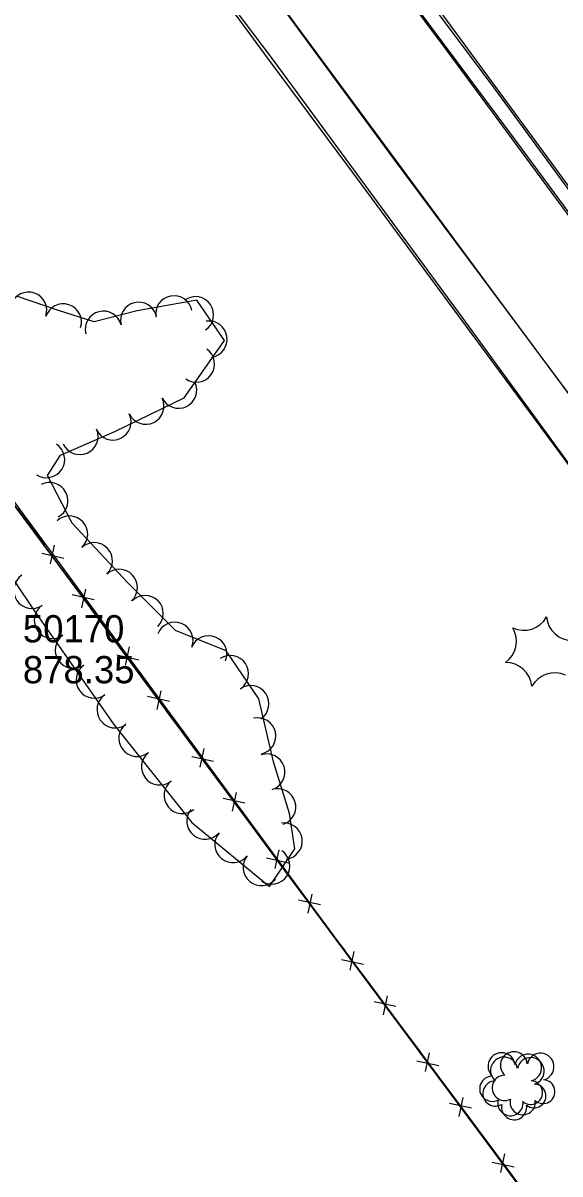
# Model space of a CAD drawing. Extents: x 353423 to 364002, y 127000 to 201942.
# Drawn here: x 360756.7 to 360874.7, y 130186.3 to 130439.6 of the extents above; entities that cross this region are included whole.
import ezdxf

# ---------------------------------------------------------------- set-up
doc = ezdxf.new("R2010")
doc.units = 0
for name, color, linetype in [('E_DTM_SlopeBottom', 7, 'Continuous'), ('E_DTM_SlopeTop', 7, 'Continuous'), ('E_FEN_Generic', 7, 'Continuous'), ('E_RDWY_AsphConc', 7, 'Continuous')]:
    doc.layers.add(name, color=color, linetype=linetype)

msp = doc.modelspace()

# ---------------------------------------------------------------- linework, layer by layer
at = {"layer": 'E_DTM_SlopeBottom'}
for p, q in [((360760.84, 130322.91), (360765.64, 130321.84)), ((360763.54, 130324.69), (360762.65, 130320.57)), ((360769.6, 130310.9), (360770.48, 130315.04)), ((360772.3, 130312.69), (360767.49, 130313.75)), ((360777.3, 130300.56), (360782.1, 130299.49)), ((360780, 130302.34), (360779.11, 130298.22)), ((360786.16, 130288.5), (360787.05, 130292.64)), ((360788.87, 130290.29), (360784.05, 130291.35)), ((360796.46, 130279.98), (360795.57, 130275.86)), ((360793.76, 130278.2), (360798.56, 130277.13)), ((360802.75, 130266.12), (360803.63, 130270.25)), ((360805.45, 130267.91), (360800.64, 130268.97)), ((360812.92, 130257.62), (360812.03, 130253.51)), ((360810.22, 130255.85), (360815.02, 130254.78)), ((360819.35, 130243.74), (360820.23, 130247.88)), ((360822.05, 130245.53), (360817.23, 130246.59)), ((360829.39, 130235.29), (360828.52, 130231.16)), ((360826.7, 130233.49), (360831.5, 130232.45)), ((360838.65, 130223.16), (360833.84, 130224.21)), ((360835.95, 130221.37), (360836.83, 130225.5)), ((360843.27, 130211.22), (360848.07, 130210.18)), ((360845.96, 130213.01), (360845.09, 130208.89)), ((360855.26, 130200.79), (360850.45, 130201.85)), ((360852.56, 130199), (360853.44, 130203.14)), ((360859.84, 130188.95), (360864.64, 130187.9)), ((360862.53, 130190.74), (360861.66, 130186.62))]:
    msp.add_line(p, q, dxfattribs=at)
for points in [[(361092.35, 129877.19), (361044.92, 129941.89), (360997.56, 130006.24), (360962.5, 130053.48), (360925.13, 130103.47), (360878.83, 130166.15), (360830.3, 130231.49), (360791.79, 130283.41), (360741.39, 130351.57), (360693.7, 130416.36), (360638.93, 130490.09), (360591.48, 130554.19), (360546.89, 130614.15), (360499.36, 130678.34), (360464.05, 130726.01), (360438.2, 130761.06), (360411.43, 130797.18), (360381.21, 130837.79)], [(360407.27, 130804.74), (360439.73, 130759.75), (360490.26, 130690.73), (360670.73, 130447.81), (360721.87, 130378.76), (360826.04, 130237.28), (360883.23, 130160.42), (360930.64, 130096.44), (361000.73, 130001.84), (361082.18, 129891.3), (361106.51, 129856.97), (361154.89, 129791.52), (361182.92, 129753.46), (361188.88, 129640.57), (361196.9, 129546.21), (361209.22, 129452.29), (361221.13, 129367.62), (361233.6, 129282.65)], [(360760.95, 130325.12), (360755.03, 130333.12)], [(360755.67, 130332.86), (360761.55, 130324.87)], [(360767.68, 130316.02), (360760.95, 130325.12)], [(360765.44, 130319.59), (360772.13, 130310.51)], [(360777.51, 130302.72), (360771.59, 130310.72)], [(360772.13, 130310.51), (360778.01, 130302.52)], [(360784.24, 130293.62), (360777.51, 130302.72)], [(360781.9, 130297.23), (360788.59, 130288.15)], [(360794.08, 130280.32), (360791.79, 130283.41), (360788.16, 130288.32)], [(360788.59, 130288.15), (360794.47, 130280.16)], [(360800.83, 130271.23), (360794.08, 130280.32)], [(360798.36, 130274.88), (360805.05, 130265.79)], [(360810.68, 130257.95), (360804.75, 130265.94)], [(360805.05, 130265.79), (360810.93, 130257.81)], [(360817.42, 130248.85), (360810.68, 130257.95)], [(360814.82, 130252.52), (360821.51, 130243.44)], [(360827.28, 130235.57), (360821.35, 130243.57)], [(360821.51, 130243.44), (360826.04, 130237.28), (360827.4, 130235.46)], [(360834.02, 130226.48), (360830.3, 130231.49), (360827.28, 130235.57)], [(360831.32, 130230.19), (360838.05, 130221.14)], [(360843.89, 130213.2), (360837.95, 130221.19)], [(360838.05, 130221.14), (360843.97, 130213.18)], [(360850.64, 130204.11), (360843.89, 130213.2)], [(360847.89, 130207.92), (360854.62, 130198.87)], [(360860.5, 130190.83), (360854.56, 130198.83)], [(360854.62, 130198.87), (360860.54, 130190.91)], [(360867.25, 130181.74), (360860.5, 130190.83)]]:
    msp.add_lwpolyline(points, dxfattribs=at)
at = {"layer": 'E_DTM_SlopeTop'}
for points in [[(361334.82, 129736.64), (361276.43, 129817.07), (361218.41, 129895.06), (361173.92, 129955.59), (361116.6, 130033.88), (361057.88, 130112.91), (361005.23, 130183.79), (360919.7, 130299.92), (360859.57, 130381.04), (360802.73, 130458.17), (360712.34, 130579.92), (360650.2, 130664.74), (360583.26, 130754.37), (360522.68, 130834.6), (360443.16, 130936.49), (360381.32, 131015.53), (360355.42, 131048.77)], [(360359.06, 131031.63), (360412.77, 130962.23), (360456.51, 130906.46), (360514.58, 130829.11), (360575.61, 130749.78), (360615.66, 130696.58), (360651.09, 130648.19), (360678.79, 130610.26), (360711.14, 130566.37), (360768.38, 130488.8), (360811.24, 130431.97), (360853.39, 130374.54), (360875.99, 130343.44), (360911.98, 130295.27), (360943.46, 130251.36), (360971.6, 130213.46), (361000.8, 130174.05), (361030.19, 130135.22), (361061.21, 130091.97), (361110.81, 130026.56), (361166.93, 129950.76), (361239.61, 129851.93), (361335.43, 129723.6)], [(360539.14, 130812.53), (360565.51, 130777.84), (360593.87, 130739.91), (360625.54, 130697.03), (360652.65, 130660.22), (360685.53, 130616.09), (360714.56, 130576.84), (360749.27, 130530.18), (360775.57, 130494.65), (360810.61, 130447.18), (360838.14, 130409.72), (360879.43, 130354.21), (360906.49, 130317.48), (360944.28, 130266.52), (360972.83, 130227.69), (361006.65, 130182.14), (361037.04, 130141.05), (361070.51, 130095.92), (361098.26, 130058.32), (361129.55, 130016.03), (361157.08, 129978.62), (361188.2, 129936.52), (361215.22, 129899.89), (361236.43, 129871.54)], [(360570.32, 130810.78), (360600.22, 130770.91), (360638.59, 130718.65), (360671.71, 130673.89), (360707.05, 130626.12), (360742.48, 130578.27), (360774.17, 130535.49), (360800.97, 130499.08), (360825.44, 130466.23), (360849.91, 130433.42), (360876.06, 130397.89), (360904.66, 130359.17), (360936.36, 130316.65), (360963.75, 130279.7), (360997.86, 130233.57), (361031.14, 130188.46), (361063.99, 130144.35), (361101.47, 130093.76), (361133.47, 130050.11), (361168.56, 130002.53), (361203.91, 129954.89), (361239.46, 129906.99), (361266.3, 129870.87)], [(360809.17, 130495.51), (360846.5, 130444.78), (360882.4, 130395.79), (360941.46, 130316.09), (360973.72, 130272.7), (361030.47, 130195.64), (361062.59, 130152.28), (361119.78, 130075.34), (361156.76, 130024.57), (361197.37, 129970), (361242.06, 129910.29), (361269.99, 129871.58), (361333.46, 129785.62)], [(361333.61, 129780.26), (361265.17, 129872.62), (361192.86, 129969.59), (361136.86, 130045.95), (361055.9, 130154.85), (360997.16, 130234.51), (360938.4, 130314.25), (360864.11, 130414.93), (360812.38, 130484.47)], [(360792.03, 130456.94), (360810.78, 130431.34), (360829.91, 130405.6), (360852.4, 130375.06), (360875.72, 130343.54), (360899.12, 130311.93), (360923, 130279.49), (360943.58, 130251.93), (360971.77, 130213.66), (361001.07, 130173.94), (361030.07, 130135.21), (361061.27, 130093.22), (361089.96, 130054.2), (361110.35, 130026.4), (361125.86, 130005.3), (361150.45, 129972.15), (361166.88, 129950.07), (361181.73, 129929.81), (361196.39, 129910.21), (361212.86, 129888.17), (361226.12, 129870.67)], [(360841.54, 130450.25), (360860.15, 130425.31), (360880.25, 130397.9), (360900.17, 130371.31), (360917.16, 130348.06), (360937.39, 130320.73), (360957.17, 130293.76), (360972.69, 130273.01), (360996.25, 130240.92), (361018.29, 130211.17), (361040.01, 130181.94), (361060.38, 130154.78), (361080.04, 130128.16), (361097.27, 130104.56), (361117.19, 130077.84), (361139.93, 130047.25), (361157.98, 130022.58), (361181.63, 129990.53), (361200.8, 129964.87), (361225.35, 129931.59), (361247.64, 129901.57), (361271.03, 129870.81)]]:
    msp.add_lwpolyline(points, dxfattribs=at)
at = {"layer": 'E_FEN_Generic'}
msp.add_lwpolyline([(360745.97, 130329.76), (360759.22, 130310.13), (360776.64, 130285.26), (360793.79, 130263.63), (360810.83, 130249.6), (360816.42, 130257.85), (360815.29, 130265.66), (360811.71, 130277.02), (360808.51, 130290.9), (360801.37, 130301.47), (360790.16, 130305.93), (360779.64, 130316.47), (360767.45, 130329.56), (360762.03, 130340.01), (360764.94, 130344.48), (360776.86, 130349.7), (360792.1, 130357.08), (360800.96, 130369.72), (360794.89, 130378.63), (360781.75, 130376.23), (360772.31, 130373.83), (360764.46, 130376.32), (360755.27, 130379.5)], dxfattribs=at)
for centre, radius, start, end in [((360757.88, 130376.37), 4.01, 340.936, 160.9207), ((360789.85, 130375.57), 4.01, 10.3566, 190.3413), ((360794.57, 130375.36), 4.01, 304.2714, 124.2561), ((360765.52, 130373.78), 4.01, 342.4224, 162.407), ((360774.34, 130372.18), 4.01, 14.2536, 194.2383), ((360782.11, 130374.15), 4.01, 14.2536, 194.2383), ((360797.52, 130370), 4.01, 278.4554, 98.4401), ((360794.78, 130364.55), 4.01, 235.0023, 54.9869), ((360790.86, 130358.81), 4.01, 205.8677, 25.8523), ((360783.65, 130355.31), 4.01, 205.8677, 25.8523), ((360776.43, 130351.82), 4.01, 205.8677, 25.8523), ((360769.17, 130348.62), 4.01, 203.6219, 23.6066), ((360761.83, 130343.54), 4.01, 236.9752, 56.9599), ((360762.54, 130334.46), 4.01, 297.4392, 117.4239), ((360766.88, 130327.1), 4.01, 312.982, 132.9667), ((360772.34, 130321.23), 4.01, 312.982, 132.9667), ((360758.64, 130314.75), 4.01, 124.046, 304.0307), ((360777.81, 130315.37), 4.01, 312.982, 132.9667), ((360783.51, 130309.63), 4.01, 314.9342, 134.9189), ((360763.16, 130308.17), 4.01, 125.0077, 304.9924), ((360790.04, 130303.72), 4.01, 338.2839, 158.2685), ((360866.77, 130311.67), 5.72, 245.1518, 330.9167), ((360877.47, 130309.4), 5.72, 185.1518, 270.9167), ((360767.76, 130301.6), 4.01, 125.0077, 304.9924), ((360859.45, 130303.53), 5.72, 305.1518, 30.9167), ((360797.48, 130300.75), 4.01, 338.2839, 158.2685), ((360802.25, 130296.42), 4.01, 304.0678, 124.0525), ((360772.35, 130295.03), 4.01, 125.0077, 304.9924), ((360862.84, 130293.13), 5.72, 5.1518, 90.9167), ((360873.55, 130290.86), 5.72, 65.1518, 150.9167), ((360806.74, 130289.78), 4.01, 304.0678, 124.0525), ((360776.95, 130288.47), 4.01, 125.0077, 304.9924), ((360781.74, 130282.2), 4.01, 128.4211, 308.4058), ((360808.25, 130282.68), 4.01, 282.9929, 102.9776), ((360786.72, 130275.92), 4.01, 128.4211, 308.4058), ((360810.23, 130274.74), 4.01, 287.5163, 107.501), ((360791.71, 130269.63), 4.01, 128.4211, 308.4058), ((360812.64, 130267.09), 4.01, 287.5163, 107.501), ((360796.68, 130263.97), 4.01, 140.5384, 320.5231), ((360814.06, 130259.57), 4.01, 278.2466, 98.2313), ((360802.87, 130258.87), 4.01, 140.5384, 320.5231), ((360811.33, 130254.08), 4.01, 235.8969, 55.8816), ((360809.06, 130253.77), 4.01, 140.5384, 320.5231), ((360861.89, 130210.03), 2.97, 6.3758, 227.6096), ((360862.43, 130209.07), 2.97, 8.3641, 229.598), ((360864.6, 130210.24), 2.97, 6.3758, 227.6096), ((360867.73, 130209.71), 2.97, 284.0266, 166.9998), ((360868.28, 130208.95), 2.97, 286.0149, 168.9882), ((360870.45, 130209.92), 2.97, 284.0266, 166.9998), ((360859.85, 130205.06), 2.78, 89.3466, 297.1196), ((360860.56, 130204.03), 2.78, 91.335, 299.108), ((360862.57, 130205.26), 2.78, 89.3466, 297.1196), ((360868.3, 130204.22), 2.61, 228.7318, 86.6644), ((360871.02, 130204.42), 2.61, 228.7318, 86.6644), ((360869.04, 130203.48), 2.61, 230.7202, 88.6528), ((360863.82, 130201.91), 2.78, 166.0237, 7.0347), ((360864.64, 130201.02), 2.78, 168.012, 9.0231), ((360866.53, 130202.12), 2.78, 166.0237, 7.0347)]:
    msp.add_arc(centre, radius, start, end, dxfattribs=at)

# ---------------------------------------------------------------- texts
at = {"layer": 'E_RDWY_AsphConc'}
for s, p in [('50170', (360756.64, 130303.29)), ('878.35', (360756.64, 130294.29))]:
    msp.add_text(s, height=6, dxfattribs=at).set_placement(p)

doc.saveas('drawing.dxf')
